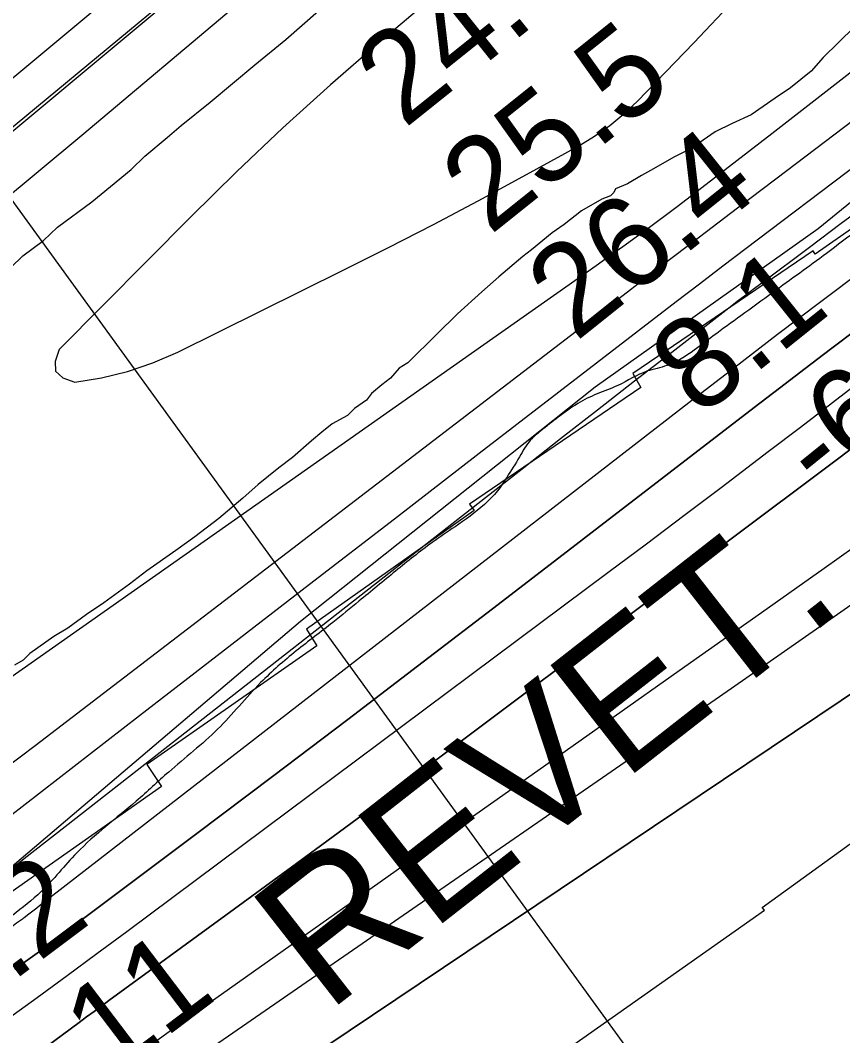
# Model space of a CAD drawing. Extents: x 3324104 to 3361979, y 612876 to 638273.
# Drawn here: x 3351130 to 3351732, y 619634 to 620377 of the extents above; entities that cross this region are included whole.
import ezdxf

# ---------------------------------------------------------------- set-up
doc = ezdxf.new("R2010")
doc.units = 0
for name, color, linetype in [('V-FLOD-BASE', 7, 'Continuous'), ('V-LEVE-TOET', 7, 'Continuous'), ('V-RIVR-EDGE', 7, 'Continuous'), ('V-RIVR-RANG', 7, 'Continuous'), ('V-RRAP-FSHR', 7, 'Continuous'), ('V-RRAP-RVMT', 7, 'Continuous'), ('V-RRAP-RVMT-IDEN', 7, 'Continuous'), ('V-SITE-VEGE', 7, 'Continuous'), ('V-SURV-LINE', 7, 'Continuous'), ('V-TOPO-DPTH', 7, 'Continuous'), ('V-TOPO-MAJR', 7, 'Continuous'), ('V-TOPO-MINR', 7, 'Continuous'), ('V-TOPO-WATR', 7, 'Continuous')]:
    doc.layers.add(name, color=color, linetype=linetype)

msp = doc.modelspace()

# ---------------------------------------------------------------- linework, layer by layer
at = {"layer": 'V-FLOD-BASE'}
msp.add_lwpolyline([(3350523.13, 619796.89), (3350632.77, 619886.53), (3350737.58, 619974.45), (3350854.29, 620072.77), (3350972.31, 620171.08), (3351089.46, 620269.83), (3351247.1, 620400.19), (3351425.46, 620549.17), (3351644.33, 620732.38), (3351747.36, 620815.94)], dxfattribs=at)
at = {"layer": 'V-LEVE-TOET'}
msp.add_lwpolyline([(3350503.77, 619731.86), (3350567.63, 619786.44), (3350623.1, 619830.16), (3350686.08, 619884.75), (3350764.92, 619951.45), (3350876.76, 620043.69), (3350972.78, 620125.56), (3351050.27, 620188.78), (3351175.33, 620292.72), (3351290.71, 620389.73), (3351390.21, 620469.39), (3351433.81, 620505.77), (3351575.19, 620627.07), (3351722.28, 620750.5), (3351767.62, 620785.55)], dxfattribs=at)
at = {"layer": 'V-RIVR-EDGE'}
msp.add_spline([(3356051.95, 622889.63), (3356029.15, 622881.43), (3356012.46, 622875.66), (3355994.6, 622867.17), (3355977.52, 622859.07), (3355958.5, 622850.97), (3355948.4, 622843.24), (3355934.03, 622834.75), (3355904.12, 622817.76), (3355878.1, 622802.31), (3355856.74, 622790.34), (3355829.95, 622776.44), (3355805.11, 622765.65), (3355764.72, 622744.81), (3355744.14, 622733.61), (3355694.06, 622710.85), (3355668.43, 622698.12), (3355641.64, 622685), (3355605.15, 622669.19), (3355569.44, 622657.26), (3355539.17, 622646.47), (3355510.83, 622636.85), (3355482.11, 622628.39), (3355461.93, 622623.01), (3355442.52, 622614.14), (3355422.73, 622607.21), (3355409.53, 622603.36), (3355388.97, 622597.59), (3355371.88, 622589.49), (3355348.98, 622581.02), (3355297.71, 622547.02), (3355260.04, 622525.78), (3355211.1, 622494.49), (3355190.13, 622484.46), (3355184.7, 622482.92), (3355179.26, 622477.89), (3355174.21, 622475.58), (3355160.62, 622470.96), (3355143.54, 622463.63), (3355133.06, 622457.07), (3355125.67, 622450.49), (3355113.25, 622443.93), (3355096.93, 622433.11), (3355081.02, 622426.95), (3355064.32, 622419.23), (3355056.95, 622418.86), (3355048.8, 622414.62), (3355041.8, 622406.88), (3355036.76, 622406.5), (3355031.32, 622405.74), (3355027.05, 622404.2), (3355017.34, 622396.08), (3355010.74, 622394.93), (3355001.42, 622388.36), (3354988.6, 622379.09), (3354972.29, 622369.43), (3354947.44, 622356.31), (3354937.73, 622351.68), (3354926.08, 622343.56), (3354903.15, 622326.56), (3354891.11, 622318.06), (3354883.33, 622307.22), (3354879.44, 622304.12), (3354875.17, 622302.58), (3354867.8, 622299.11), (3354853.03, 622288.29), (3354842.54, 622279.01), (3354826.61, 622267.41), (3354807.2, 622259.71), (3354793.23, 622255.47), (3354765.68, 622249.73), (3354748.61, 622245.5), (3354734.63, 622239.33), (3354712.11, 622227.37), (3354697.74, 622218.87), (3354685.31, 622209.98), (3354640.65, 622184.5), (3354622.01, 622176.01), (3354616.19, 622175.25), (3354603.38, 622167.52), (3354578.92, 622157.11), (3354554.46, 622147.48), (3354537.39, 622142.87), (3354530.78, 622137.84), (3354500.11, 622122.79), (3354463.61, 622102.33), (3354417.79, 622078.79), (3354386.33, 622060.64), (3354340.11, 622032.44), (3354321.08, 622021.25), (3354284.96, 621998.84), (3354257, 621982.24), (3354217, 621958.68), (3354194.08, 621942.84), (3354176.99, 621931.63), (3354157.57, 621921.98), (3354141.64, 621910.39), (3354135.42, 621904.2), (3354130.36, 621897.62), (3354120.65, 621891.05), (3354103.96, 621882.95), (3354075.58, 621856.65), (3354044.89, 621835.39), (3354013.04, 621812.21), (3353971.47, 621781.67), (3353947.77, 621763.5), (3353941.17, 621763.52), (3353935.35, 621762.76), (3353929.53, 621760.06), (3353924.87, 621756.58), (3353920.59, 621751.55), (3353917.08, 621742.64), (3353910.48, 621741.49), (3353904.66, 621738.4), (3353893.78, 621731.06), (3353879.8, 621721.4), (3353866.19, 621708.64), (3353854.92, 621697.42), (3353843.26, 621687.75), (3353839.77, 621688.54), (3353831.23, 621686.23), (3353823.08, 621681.21), (3353818.03, 621677.34), (3353800.94, 621666.14), (3353790.85, 621663.06), (3353781.91, 621654.94), (3353777.63, 621651.85), (3353776.07, 621648.75), (3353775.67, 621643.71), (3353772.18, 621641), (3353755.87, 621632.13), (3353735.68, 621622.09), (3353718.58, 621608.17), (3353704.21, 621600.45), (3353694.12, 621596.6), (3353683.64, 621592.36), (3353671.21, 621584.25), (3353642.07, 621562.99), (3353598.95, 621534.01), (3353578.37, 621522.43), (3353556.23, 621507.75), (3353547.68, 621501.95), (3353525.93, 621489.21), (3353513.12, 621481.09), (3353497.18, 621468.34), (3353476.98, 621450.94), (3353453.28, 621436.65), (3353435.8, 621424.67), (3353404.72, 621401.09), (3353378.3, 621380.21), (3353361.59, 621368.62), (3353339.46, 621355.1), (3353319.65, 621342.35), (3353299.45, 621329.99), (3353283.54, 621324.6), (3353273.05, 621317.65), (3353254.77, 621295.98), (3353236.88, 621275.47), (3353219.39, 621258.83), (3353195.69, 621241.44), (3353168.49, 621221.34), (3353137.81, 621201.64), (3353112.17, 621185.03), (3353065.55, 621151.79), (3353022.05, 621122.82), (3352993.29, 621100.39), (3352956, 621073.34), (3352907.05, 621037.78), (3352853.8, 620991.77), (3352787.76, 620942.29), (3352749.68, 620913.3), (3352736.85, 620900.92), (3352733.34, 620892.79), (3352728.67, 620886.59), (3352718.96, 620881.19), (3352691.78, 620864.58), (3352660.31, 620841.78), (3352640.5, 620828.25), (3352623.39, 620811.23), (3352605.12, 620792.27), (3352593.46, 620783), (3352582.59, 620778.76), (3352566.29, 620771.43), (3352548.04, 620764.49), (3352522.41, 620750.98), (3352494.45, 620735.54), (3352482.41, 620727.04), (3352479.3, 620723.17), (3352476.96, 620717.36), (3352470.74, 620711.94), (3352455.99, 620707.33), (3352443.18, 620700.38), (3352419.1, 620685.7), (3352392.3, 620669.09), (3352362.78, 620650.94), (3352339.08, 620634.32), (3352315.38, 620615.38), (3352284.68, 620590.63), (3352258.65, 620571.31), (3352228.74, 620550.05), (3352193.39, 620527.65), (3352156.88, 620504.86), (3352131.63, 620487.47), (3352093.95, 620462.36), (3352049.28, 620432.99), (3351990.23, 620391.26), (3351936.63, 620357.26), (3351851.55, 620293.87), (3351833.29, 620281.51), (3351816.98, 620273.79), (3351794.06, 620257.95), (3351767.65, 620240.95), (3351719.86, 620206.17), (3351680.63, 620177.57), (3351657.32, 620160.56), (3351637.11, 620145.87), (3351623.13, 620135.44), (3351603.32, 620124.24), (3351588.57, 620120.01), (3351567.22, 620109.59), (3351552.08, 620103.43), (3351538.1, 620096.48), (3351523.73, 620086.43), (3351510.91, 620076.38), (3351503.52, 620069.81), (3351495.35, 620057.42), (3351486, 620042.32), (3351479.39, 620032.64), (3351469.67, 620022.58), (3351448.3, 620006.34), (3351431.59, 619994.75), (3351404.78, 619973.88), (3351377.97, 619951.84), (3351358.93, 619936.37), (3351332.12, 619915.5), (3351306.08, 619892.29), (3351274.58, 619858.25), (3351238.83, 619826.92), (3351215.12, 619805.65), (3351171.59, 619767.75), (3351145.54, 619739.51), (3351124.55, 619722.11), (3351105.9, 619707.81), (3351089.59, 619696.99), (3351079.49, 619691.2), (3351074.04, 619683.45), (3351058.1, 619666.43), (3351043.34, 619655.22), (3351015.36, 619633.96), (3350999.05, 619623.14), (3350992.05, 619617.34), (3350979.23, 619606.13), (3350966.01, 619594.53), (3350951.25, 619582.15), (3350935.7, 619567.84), (3350923.26, 619555.08), (3350910.05, 619544.25), (3350888.29, 619528.02), (3350846.74, 619504.08), (3350821.49, 619490.18), (3350811.39, 619483.61), (3350805.96, 619480.52), (3350800.9, 619473.16), (3350797.41, 619473.17), (3350793.92, 619474.35), (3350788.88, 619473.58), (3350786.93, 619472.04), (3350785.37, 619467.39), (3350785.36, 619462.73), (3350779.53, 619456.15), (3350765.93, 619445.72), (3350746.11, 619428.7), (3350722.4, 619408.98), (3350716.19, 619407.06), (3350713.08, 619403.96), (3350711.13, 619396.99), (3350708.79, 619391.57), (3350704.52, 619391.58), (3350693.26, 619385.79), (3350686.65, 619379.6), (3350679.64, 619368.37), (3350661.38, 619354.45), (3350648.56, 619344.4), (3350645.46, 619344.8), (3350638.47, 619339.39), (3350623.32, 619330.5), (3350616.33, 619326.26), (3350602.35, 619317.37), (3350598.83, 619308.85), (3350582.91, 619299.19), (3350553.77, 619276), (3350526.18, 619255.51), (3350493.55, 619231.94), (3350474.9, 619219.57), (3350474.5, 619213.76), (3350470.22, 619207.17), (3350458.96, 619202.55), (3350446.14, 619194.05), (3350441.09, 619189.79), (3350438.76, 619186.31), (3350434.48, 619180.89), (3350414.67, 619167.76), (3350401.46, 619159.26), (3350384.75, 619146.89), (3350369.6, 619133.74), (3350356.39, 619125.24), (3350350.95, 619119.05), (3350347.43, 619109.36), (3350338.1, 619097.75), (3350324.88, 619083.82), (3350308.55, 619069.9), (3350300.39, 619062.56), (3350296.13, 619062.57), (3350291.47, 619062.19), (3350274.77, 619050.6), (3350258.45, 619037.45), (3350251.84, 619032.81), (3350244.08, 619029.34), (3350233.61, 619028.21), (3350227.39, 619024.34), (3350220.39, 619016.99), (3350213, 619007.32), (3350202.12, 618996.87), (3350193.57, 618989.52), (3350179.6, 618985.29), (3350173.77, 618980.65), (3350164.84, 618977.96), (3350162.12, 618975.25), (3350159.39, 618971.38), (3350154.33, 618963.64), (3350145.78, 618953.19), (3350125.96, 618938.11), (3350102.66, 618923.05), (3350094.5, 618918.41), (3350086.34, 618913), (3350075.07, 618901.01), (3350064.19, 618892.12), (3350039.32, 618873.57), (3350021.84, 618861.59), (3350002.03, 618848.84), (3349991.94, 618844.21), (3349964.36, 618826.44), (3349938.72, 618807.11), (3349915.41, 618792.82), (3349892.5, 618778.92), (3349868.02, 618761.91), (3349852.49, 618753.03), (3349842.79, 618749.95), (3349830.35, 618739.13), (3349804.32, 618720.19), (3349777.9, 618697.76), (3349751.86, 618677.66), (3349729.72, 618661.43), (3349703.69, 618642.88), (3349678.84, 618629.75), (3349648.93, 618611.99), (3349624.46, 618594.99), (3349592.61, 618575.67), (3349570.48, 618564.87), (3349549.5, 618548.63), (3349505.21, 618518.11), (3349479.19, 618499.94), (3349471.42, 618494.53), (3349458.99, 618487.59), (3349438.4, 618472.12), (3349412.37, 618452.41), (3349379.73, 618429.61), (3349350.21, 618410.29), (3349303.2, 618374.73), (3349277.56, 618357.73), (3349263.97, 618347.29), (3349241.43, 618330.68), (3349226.67, 618319.85), (3349207.25, 618306.33), (3349193.17, 618293.54)], degree=3, dxfattribs=at)
at = {"layer": 'V-RIVR-RANG'}
msp.add_line((3351091.44, 620289.61), (3351678.93, 619480.37), dxfattribs=at)
at = {"layer": 'V-RRAP-FSHR'}
msp.add_lwpolyline([(3349156.55, 618293.48), (3349290.84, 618378.98), (3349409.37, 618477.79), (3349541.25, 618565.26), (3349771.64, 618715.9), (3349922.45, 618808.45), (3350215.79, 619019.76), (3350269.12, 619069.35), (3350501.35, 619248.31), (3350630.24, 619348.58), (3350981.59, 619636.83), (3351335.34, 619937.32), (3351550.69, 620108.65), (3351713.66, 620224.46), (3351812.36, 620304.63), (3352053.37, 620458.3), (3352414.71, 620728.03), (3352590.48, 620825.76), (3352682.34, 620894.14), (3352964.07, 621108.39), (3353211.76, 621284.79), (3354078.79, 621880.27)], dxfattribs=at)
at = {"layer": 'V-RRAP-RVMT'}
for p, q in [((3351828.24, 620286.89), (3351711.5, 620205.67)), ((3351710.08, 620208.05), (3351578.33, 620118.31)), ((3351711.5, 620205.67), (3351710.08, 620208.05)), ((3351578.33, 620118.31), (3351584.18, 620108.08)), ((3351584.18, 620108.08), (3351458.82, 620022.9)), ((3351458.82, 620022.9), (3351462.26, 620018.08)), ((3351462.26, 620018.08), (3351339.58, 619931.5)), ((3351339.58, 619931.5), (3351347.27, 619919.31)), ((3351347.27, 619919.31), (3351222.89, 619832.47)), ((3351222.89, 619832.47), (3351233.48, 619816.42)), ((3351672.84, 619727.74), (3351797.82, 619818.44)), ((3351233.48, 619816.42), (3351110, 619729.64)), ((3351424.98, 619550.19), (3351674.44, 619725.82)), ((3351674.44, 619725.82), (3351672.84, 619727.74))]:
    msp.add_line(p, q, dxfattribs=at)
at = {"layer": 'V-SITE-VEGE'}
for points in [[(3351123.49, 620195.83), (3351132.3, 620204.49), (3351147.36, 620215.6), (3351157.42, 620225.49), (3351182.53, 620244), (3351196.35, 620255.12), (3351211.43, 620267.47), (3351221.49, 620277.37), (3351237.82, 620290.97), (3351247.88, 620299.62), (3351269.23, 620316.91), (3351301.9, 620344.1), (3351324.51, 620362.63), (3351348.39, 620383.64)], [(3351740.1, 620371.69), (3351717.46, 620349.42), (3351708.64, 620339.51), (3351693.56, 620327.16), (3351682.27, 620319.76), (3351664.7, 620307.42), (3351650.93, 620301.3), (3351638.4, 620295.16), (3351620.83, 620282.83), (3351608.3, 620276.69), (3351593.25, 620268.08), (3351584.48, 620263.16), (3351574.45, 620257.01), (3351565.68, 620253.33), (3351564.41, 620250.85), (3351561.9, 620248.37), (3351555.64, 620245.93), (3351540.6, 620237.32), (3351528.04, 620227.44), (3351519.25, 620221.27), (3351504.17, 620208.92), (3351497.9, 620203.98), (3351480.31, 620189.15), (3351467.74, 620178.02), (3351450.13, 620161.95), (3351435.04, 620147.1), (3351413.66, 620126.06), (3351407.39, 620122.37), (3351401.08, 620114.94), (3351394.81, 620109.99), (3351387.27, 620103.82), (3351383.48, 620098.86), (3351374.7, 620092.69), (3351369.67, 620087.74), (3351358.39, 620081.59), (3351350.85, 620075.42), (3351343.31, 620069.24)], [(3351343.31, 620069.24), (3351329.48, 620056.88), (3351319.44, 620049.47), (3351304.37, 620037.12), (3351293.05, 620027.23), (3351275.46, 620012.4), (3351257.88, 619998.82), (3351244.07, 619988.95), (3351222.74, 619974.15), (3351210.18, 619964.27), (3351191.35, 619950.7), (3351178.8, 619942.07), (3351165, 619932.2), (3351154.97, 619926.04), (3351137.4, 619913.71)], [(3351137.4, 619913.71), (3351132.36, 619908.76), (3351126.09, 619905.07)]]:
    msp.add_lwpolyline(points, dxfattribs=at)
at = {"layer": 'V-SURV-LINE'}
for points in [[(3350211.96, 619573.82), (3351704.95, 620818.45)], [(3351724.16, 620795.41), (3350231.16, 619550.77)]]:
    msp.add_lwpolyline(points, dxfattribs=at)
at = {"layer": 'V-TOPO-DPTH'}
for points in [[(3351753.94, 620245.22), (3351730.62, 620227.94), (3351707.36, 620210.58), (3351673.59, 620185.28), (3351667.26, 620180.51), (3351660.95, 620175.72), (3351654.65, 620170.9), (3351648.38, 620166.06), (3351606.68, 620133.75), (3351579.58, 620112.71), (3351552.5, 620091.65), (3351525.46, 620070.54), (3351498.43, 620049.4), (3351165.34, 619788.46), (3351138.82, 619767.79), (3351112.25, 619747.19)], [(3351126.37, 619682.68), (3351137.53, 619690.79), (3351148.66, 619698.94), (3351159.74, 619707.15), (3351170.79, 619715.4), (3351259.4, 619781.98), (3351314.66, 619823.64), (3351369.83, 619865.43), (3351424.86, 619907.4), (3351479.8, 619949.5), (3351667, 620093.44), (3351685.58, 620107.71), (3351704.18, 620121.95), (3351722.81, 620136.15), (3351741.46, 620150.33)], [(3351126.37, 619682.68), (3351137.53, 619690.79), (3351148.66, 619698.94), (3351159.74, 619707.15), (3351170.79, 619715.4), (3351259.4, 619781.98), (3351314.66, 619823.64), (3351369.83, 619865.43), (3351424.86, 619907.4), (3351479.8, 619949.5), (3351667, 620093.44), (3351685.58, 620107.71), (3351704.18, 620121.95), (3351722.81, 620136.15), (3351741.46, 620150.33)], [(3350500.92, 619156.58), (3350597.73, 619225.34), (3350610.48, 619234.42), (3350623.21, 619243.52), (3350635.92, 619252.67), (3350648.6, 619261.84), (3350950.63, 619480.72), (3350989.67, 619509.08), (3351028.67, 619537.5), (3351067.61, 619566.01), (3351106.5, 619594.57), (3351173.35, 619643.79), (3351178.79, 619647.79), (3351184.23, 619651.79), (3351189.67, 619655.78), (3351195.12, 619659.76), (3351280.51, 619722.16), (3351328.59, 619757.43), (3351376.59, 619792.82), (3351424.45, 619828.38), (3351472.23, 619864.06), (3351729.95, 620057.28), (3351738.1, 620063.46)], [(3351738.1, 620063.46), (3351729.95, 620057.28), (3351472.23, 619864.06), (3351424.45, 619828.38), (3351376.59, 619792.82), (3351328.59, 619757.43), (3351280.51, 619722.16), (3351195.12, 619659.76), (3351189.67, 619655.78), (3351184.23, 619651.79), (3351178.79, 619647.79), (3351173.35, 619643.79), (3351106.5, 619594.57), (3351067.61, 619566.01), (3351028.67, 619537.5), (3350989.67, 619509.08), (3350950.63, 619480.72), (3350648.6, 619261.84), (3350635.92, 619252.67), (3350623.21, 619243.52), (3350610.48, 619234.42), (3350597.73, 619225.34), (3350500.92, 619156.58)], [(3351793.38, 619988), (3351727.81, 619942.08), (3351689.08, 619915.01), (3351650.31, 619887.99), (3351611.5, 619861.05), (3351572.65, 619834.15), (3351261.99, 619619.54), (3351244.52, 619607.29), (3351227.16, 619594.86), (3351209.99, 619582.2), (3351192.93, 619569.36), (3350921.06, 619361.8), (3350880.42, 619330.68), (3350839.84, 619299.48), (3350799.34, 619268.16), (3350758.91, 619236.77), (3350693.86, 619186.11), (3350685.96, 619180.04), (3350678, 619174.03), (3350669.98, 619168.12), (3350661.9, 619162.28), (3350597.95, 619116.62), (3350557.59, 619088.4), (3350516.88, 619060.72)], [(3351793.38, 619988), (3351727.81, 619942.08), (3351689.08, 619915.01), (3351650.31, 619887.99), (3351611.5, 619861.05), (3351572.65, 619834.15), (3351261.99, 619619.54), (3351244.52, 619607.29), (3351227.16, 619594.86), (3351209.99, 619582.2), (3351192.93, 619569.36), (3350921.06, 619361.8), (3350880.42, 619330.68), (3350839.84, 619299.48), (3350799.34, 619268.16), (3350758.91, 619236.77), (3350693.86, 619186.11), (3350685.96, 619180.04), (3350678, 619174.03), (3350669.98, 619168.12), (3350661.9, 619162.28), (3350597.95, 619116.62), (3350557.59, 619088.4), (3350516.88, 619060.72)], [(3350395.02, 618900.32), (3350654.07, 619097.36), (3350680.42, 619117.45), (3350706.75, 619137.57), (3350733.03, 619157.75), (3350759.29, 619177.96), (3351204.77, 619521.59), (3351212.95, 619527.9), (3351221.15, 619534.2), (3351229.35, 619540.49), (3351237.56, 619546.77), (3351245.83, 619552.97), (3351254.18, 619559.06), (3351262.63, 619565), (3351271.17, 619570.83), (3351275.85, 619573.96), (3351286.77, 619581.29), (3351297.7, 619588.61), (3351308.62, 619595.94), (3351319.54, 619603.27), (3351781.82, 619913.5)], [(3350686.93, 619122.42), (3350706.75, 619137.57), (3350733.03, 619157.75), (3350759.29, 619177.96), (3351204.77, 619521.59), (3351212.95, 619527.9), (3351221.15, 619534.2), (3351229.35, 619540.49), (3351237.56, 619546.77), (3351245.83, 619552.97), (3351254.18, 619559.06), (3351262.63, 619565), (3351271.17, 619570.83), (3351275.85, 619573.96), (3351286.77, 619581.29), (3351297.7, 619588.61), (3351308.62, 619595.94), (3351319.54, 619603.27), (3351781.82, 619913.5)]]:
    msp.add_lwpolyline(points, dxfattribs=at)
at = {"layer": 'V-TOPO-MAJR'}
for points in [[(3351561.4, 620299.62), (3351571.77, 620308.3), (3351581.65, 620317.64), (3351622.77, 620360.15), (3351652.42, 620391.59), (3351681.53, 620423.52), (3351709.81, 620456.18), (3351737.56, 620489.32)], [(3351440.77, 620401.23), (3351392.45, 620360.2), (3351357.14, 620329.44), (3351322.38, 620298.09), (3351288.44, 620265.86), (3351255.03, 620233.04), (3351158.77, 620135.99), (3351155.74, 620127.17), (3351156.08, 620119.97), (3351161.5, 620115.22), (3351170.29, 620112.1), (3351189.76, 620115.29), (3351208.84, 620119.79), (3351227.34, 620126.27), (3351245.46, 620134.07), (3351366.49, 620193.89), (3351399.56, 620210.5), (3351432.49, 620227.4), (3351465.2, 620244.73), (3351497.76, 620262.34), (3351538.69, 620284.83), (3351550.29, 620291.9), (3351561.4, 620299.62)], [(3351750.18, 620348.18), (3351715.12, 620320.91), (3351680.01, 620293.73), (3351611.58, 620240.96), (3351610.63, 620240.23), (3351608.72, 620238.78), (3351607.76, 620238.07), (3351590.41, 620225.21), (3351580.75, 620218.11), (3351571.06, 620211.05), (3351561.31, 620204.07), (3351551.52, 620197.14), (3351084.73, 619869.02)]]:
    msp.add_lwpolyline(points, dxfattribs=at)
at = {"layer": 'V-TOPO-MINR'}
for points in [[(3351976.54, 620483.42), (3351682.77, 620260.49), (3351654.84, 620239.27), (3351626.94, 620218.02), (3351599.06, 620196.74), (3351571.2, 620175.44), (3351141.24, 619846.18), (3351130.29, 619837.79), (3351119.35, 619829.4), (3351108.4, 619821), (3351097.46, 619812.6), (3351080.44, 619799.52), (3351078.01, 619797.66), (3351075.57, 619795.81), (3351073.13, 619793.96), (3351070.68, 619792.13), (3351038.59, 619768.12), (3351020.09, 619754.29), (3351001.59, 619740.46), (3350983.07, 619726.65), (3350964.55, 619712.85), (3350549.5, 619403.67), (3350533.02, 619391.24), (3350516.63, 619378.69)], [(3351772.38, 620293.8), (3351678.23, 620222.81), (3351661.09, 620209.85), (3351643.97, 620196.84), (3351626.89, 620183.78), (3351609.84, 620170.69), (3351465.98, 620059.84), (3351403.85, 620011.94), (3351341.74, 619964.02), (3351279.65, 619916.06), (3351217.59, 619868.07), (3351121.83, 619794)], [(3351753.94, 620245.22), (3351730.62, 620227.94), (3351707.36, 620210.58), (3351673.59, 620185.28), (3351667.26, 620180.51), (3351660.95, 620175.72), (3351654.65, 620170.9), (3351648.38, 620166.06), (3351606.68, 620133.75), (3351579.58, 620112.71), (3351552.5, 620091.65), (3351525.46, 620070.54), (3351498.43, 620049.4), (3351165.34, 619788.46), (3351138.82, 619767.79), (3351112.25, 619747.19)], [(3351747.23, 620194.54), (3351715.65, 620170.75), (3351684.14, 620146.86), (3351652.76, 620122.82), (3351621.44, 620098.67), (3351144.46, 619728.99), (3351142.51, 619727.48), (3351140.56, 619725.99), (3351136.65, 619723.01), (3351133.13, 619720.35), (3351132.32, 619719.75), (3351131.91, 619719.45), (3351127.59, 619716.3), (3351125.02, 619714.42), (3351122.46, 619712.54), (3351119.9, 619710.65), (3351117.34, 619708.76), (3350612.45, 619332.91), (3350593.69, 619318.84), (3350574.98, 619304.68), (3350556.37, 619290.4), (3350537.82, 619276.04), (3350162.62, 618983.47)], [(3351747.74, 620114.93), (3351724.29, 620096.94), (3351700.82, 620078.99), (3351677.32, 620061.05), (3351670.01, 620055.47), (3351642.82, 620034.81), (3351615.58, 620014.2), (3351588.28, 619993.67), (3351560.93, 619973.21), (3351208.14, 619710), (3351186.4, 619693.87), (3351164.58, 619677.83), (3351142.68, 619661.91), (3351120.72, 619646.07)], [(3351738.1, 620063.46), (3351729.95, 620057.28), (3351472.23, 619864.06), (3351424.45, 619828.38), (3351376.59, 619792.82), (3351328.59, 619757.43), (3351280.51, 619722.16), (3351195.12, 619659.76), (3351189.67, 619655.78), (3351184.23, 619651.79), (3351178.79, 619647.79), (3351173.35, 619643.79), (3351106.5, 619594.57), (3351067.61, 619566.01), (3351028.67, 619537.5), (3350989.67, 619509.08), (3350950.63, 619480.72), (3350648.6, 619261.84), (3350635.92, 619252.67), (3350623.21, 619243.52), (3350610.48, 619234.42), (3350597.73, 619225.34), (3350500.92, 619156.58)], [(3351750.98, 619999.25), (3351718.07, 619975.66), (3351672.34, 619943.41), (3351616.38, 619903.92), (3351560.44, 619864.41), (3351504.52, 619824.88), (3351448.61, 619785.33), (3351267.51, 619657.16), (3351239.15, 619636.86), (3351210.96, 619616.35), (3351182.99, 619595.52), (3351155.18, 619574.48), (3350837.56, 619331.38), (3350807.99, 619308.91), (3350778.31, 619286.58), (3350748.47, 619264.47), (3350718.53, 619242.5), (3350688.31, 619220.94), (3350657.8, 619199.78), (3350626.89, 619179.23), (3350595.69, 619159.09), (3350255.13, 618943.95)], [(3351793.38, 619988), (3351727.81, 619942.08), (3351689.08, 619915.01), (3351650.31, 619887.99), (3351611.5, 619861.05), (3351572.65, 619834.15), (3351261.99, 619619.54), (3351244.52, 619607.29), (3351227.16, 619594.86), (3351209.99, 619582.2), (3351192.93, 619569.36), (3350921.06, 619361.8), (3350880.42, 619330.68), (3350839.84, 619299.48), (3350799.34, 619268.16), (3350758.91, 619236.77), (3350693.86, 619186.11), (3350685.96, 619180.04), (3350678, 619174.03), (3350669.98, 619168.12), (3350661.9, 619162.28), (3350597.95, 619116.62), (3350557.59, 619088.4), (3350516.88, 619060.72)], [(3351781.82, 619913.5), (3351319.54, 619603.27), (3351308.62, 619595.94), (3351297.7, 619588.61), (3351286.77, 619581.29), (3351275.85, 619573.96), (3351271.17, 619570.83), (3351262.63, 619565), (3351254.18, 619559.06), (3351245.83, 619552.97), (3351237.56, 619546.77), (3351229.35, 619540.49), (3351221.15, 619534.2), (3351212.95, 619527.9), (3351204.77, 619521.59), (3350759.29, 619177.96), (3350733.03, 619157.75), (3350706.75, 619137.57), (3350680.42, 619117.45), (3350654.07, 619097.36), (3350395.02, 618900.32)]]:
    msp.add_lwpolyline(points, dxfattribs=at)
at = {"layer": 'V-TOPO-WATR'}
msp.add_lwpolyline([(3351741.46, 620150.33), (3351722.81, 620136.15), (3351704.18, 620121.95), (3351685.58, 620107.71), (3351667, 620093.44), (3351479.8, 619949.5), (3351424.86, 619907.4), (3351369.83, 619865.43), (3351314.66, 619823.64), (3351259.4, 619781.98), (3351170.79, 619715.4), (3351159.74, 619707.15), (3351148.66, 619698.94), (3351137.53, 619690.79), (3351126.37, 619682.68)], dxfattribs=at)

# ---------------------------------------------------------------- texts
at = {"layer": 'V-RIVR-RANG'}
for s, rotation, p in [('24.7', 38.65833, (3351411.09, 620296.92)), ('25.5', 38.65833, (3351473.75, 620218.98)), ('26.4', 38.65833, (3351536.42, 620141.05)), ('8.1', 38.65833, (3351626.88, 620085.36)), ('-6', 38.94153, (3351716.19, 620028.43)), ('6.2', 36.88833, (3351083.88, 619642.75)), ('-11', 37.17528, (3351172.24, 619583.72))]:
    msp.add_text(s, height=67, rotation=rotation, dxfattribs=at).set_placement(p)
at = {"layer": 'V-RRAP-RVMT-IDEN'}
msp.add_text('REVET.', height=100, rotation=38.03078, dxfattribs=at).set_placement((3351354.45, 619650.12))

doc.saveas('drawing.dxf')
